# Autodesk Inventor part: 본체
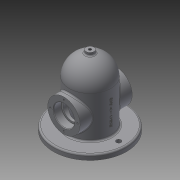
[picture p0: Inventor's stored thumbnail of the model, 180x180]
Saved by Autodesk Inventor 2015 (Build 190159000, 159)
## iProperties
Created: 2019-11
Part Number: 본체
Material: 일반
Document SubType Name: Modeling
Designer: Line503_02
Density: 1 g/cm^3
Appearance: 기본값
Author: Line503_02
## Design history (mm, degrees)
sketch "스케치1"
  geometry: C1 r 70 at (0, 0); 1 further point
  constraints: 1 centre point, 1 coincident
  dimensions: "d0" = 140 diameter of C1
extrude "돌출1" new body sketch "스케치1" distance "d1" = 10; taper "d2" = 0 deg
sketch "스케치2"
  geometry: C1 r 40 at (0, 0); 1 further point
  constraints: 1 centre point, 1 coincident
  dimensions: "d3" = 80 diameter of C1
extrude "돌출2" join sketch "스케치2" distance "d4" = 80; taper "d5" = 0 deg
sketch "스케치3"
  geometry: L1 (40, 90)-(-40, 90) reference; L2 (0, 130)-(0, 90); L3 (40, 90)-(0, 90); A1 r 40 centre (0, 90) between (40, 90) and (0, 130); 1 further point
  constraints: 5 end point, 2 point on circle, 1 centre point, 1 midpoint, 1 perpendicular, 1 vertical
revolve "회전1" sketch "스케치3" stored, may be unused: angle "d6" = 90 deg
sketch "스케치4"
  geometry: L1 (-50, 81)-(50, 81); L2 (50, 81)-(50, 50); L3 (50, 50)-(-50, 50); L4 (-50, 50)-(-50, 81); 1 further point
  constraints: 8 end point, 2 parallel, 1 horizontal, 1 perpendicular
  dimensions: "d7" = 50 distance from line of L3 point (0, 0); "d8" = 100 distance of L2.end L3.end; "d9" = 50 distance from line of point (0, 0) L4; "d10" = 62 diameter of L1 L3
revolve "회전2" sketch "스케치4" stored, may be unused: angle "d11" = 90 deg
sketch "스케치5"
  geometry: L1 (40, 10)-(40, 90) reference; L2 (0, 0)-(0, 120); L3 (0, 0)-(30, 0); L4 (30, 0)-(30, 90); A1 r 40 centre (0, 90) between (40, 90) and (-40, 90) reference; A2 r 30 centre (0, 90) between (30, 90) and (0, 120)
  constraints: 6 end point, 2 point on circle, 1 centre point, 1 horizontal, 1 parallel, 1 vertical
  dimensions: "d12" = 10 distance between parallel lines of L1 L4; "d13" = 10 radial gap between concentric circles of A1 A2
revolve "회전3" sketch "스케치5" stored, may be unused: angle "d14" = 90 deg
hole "구멍1" diameter "d17" = 33; stored, may be unused: countersink angle "d21" = 90 deg, drill point angle "d23" = 118 deg; dims "d15" = 10, "d16" = 10, "d18" = 6, "d19" = 40, "d20" = 15, "d22" = 37
sketch "스케치6"
  geometry: C1 r 31 at (0, 0) reference; 2 further points
  constraints: 1 vertical alignment
  dimensions: "d24" = 26 distance of point (0, 26) C1.centre
hole "구멍2" sketch "스케치6" at (0, 26) diameter "d25" = 3.242; stored, may be unused: countersink angle "d29" = 90 deg, drill point angle "d31" = 118 deg; dims "d26" = 8, "d27" = 40, "d28" = 15, "d30" = 10
sketch "스케치7"
  geometry: C1 r 4.5 at (-55, 0); C2 r 4.5 at (55, 0); 1 further point
  constraints: 3 horizontal alignment, 2 centre point
  dimensions: "d35" = 55 distance of C1.centre point (0, 0); "d36" = 55 distance of C2.centre point (0, 0) (= d35); "d37" = 9 diameter of C1; "d38" = 9 diameter of C2
extrude "돌출3" cut sketch "스케치7" distance "d39" = 80; taper "d40" = 0 deg
node "작업 평면1"
sketch "스케치8"
  geometry: L1 (-70, -10)-(70, -10) reference; 2 further points
  constraints: 1 vertical alignment, 1 other
  dimensions: "d41" = 50 distance from line of point (0, 40) L1
feature "엠보싱1" sketch "스케치8" dims "d42" = 0.5, "d43" = 0
node "작업 평면2"
sketch "스케치9"
  geometry: C1 r 7.5 at (0, 0); 1 further point
  constraints: 1 centre point, 1 coincident
  dimensions: "d45" = 15 diameter of C1
extrude "돌출4" join sketch "스케치9" stored distance "d46" = 80; taper "d47" = 0 deg
hole "구멍3" diameter "d50" = 5.188; stored, may be unused: countersink angle "d54" = 90 deg, drill point angle "d56" = 118 deg; dims "d48" = 10, "d49" = 10, "d51" = 12, "d52" = 40, "d53" = 15, "d55" = 16
fillet "모깎기1" dims "d57" = 3
fillet "모깎기2" dims "d58" = 0.3
chamfer "모따기1" distance "d59" = 1; stored, may be unused: second distance "d60" = 2, angle "d61" = 45 deg
node "솔리드1"
pattern_circular "원형 패턴1" dims angle "d33" = 360 deg
mirror "대칭1"
other parameters: "d44" = -135
